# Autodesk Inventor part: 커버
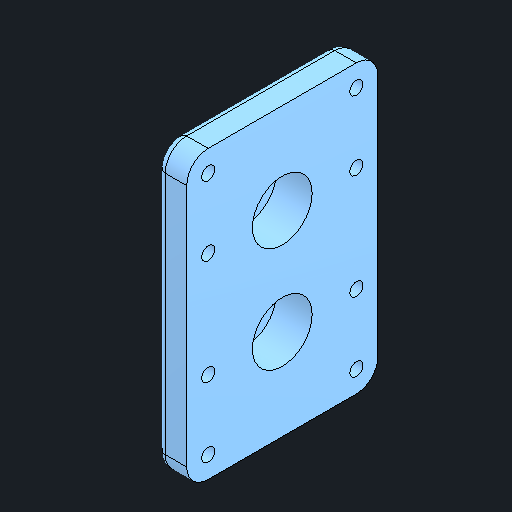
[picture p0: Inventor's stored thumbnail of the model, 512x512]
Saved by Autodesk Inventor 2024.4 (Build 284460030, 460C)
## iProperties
Created: 2026-09
Part Number: 커버
Material: 알루미늄 6061
Document SubType Name: Modeling
Designer: user
Density: 2.71 g/cm^3
Appearance: 기본값
Author: jhkim
Sending System: Autodesk Inventor 2027
Preprocessor: ST-DEVELOPER v20.1
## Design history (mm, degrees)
feature "솔리드1"
node "솔리드2"
